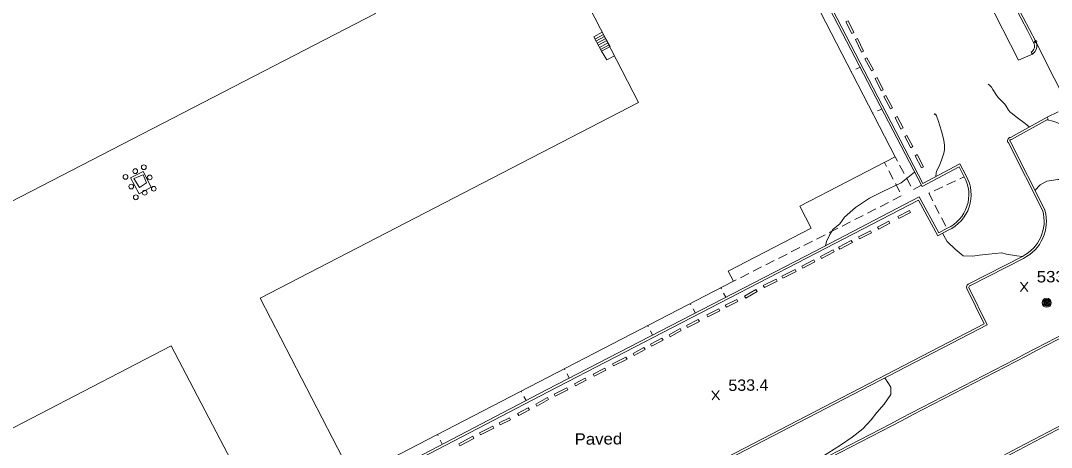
# Model space of a CAD drawing. Extents: x 2361284 to 2366480, y 6976556 to 6985346.
# Drawn here: x 2362953.7 to 2363387.8, y 6978671.2 to 6978850.6 of the extents above; entities that cross this region are included whole.
import ezdxf

# ---------------------------------------------------------------- set-up
doc = ezdxf.new("R2010")
doc.units = 0
doc.header["$LTSCALE"] = 1.9
doc.header["$PDMODE"] = 32
doc.header["$PDSIZE"] = 0.95
for name, color, linetype, lineweight in [('10', 7, 'Continuous', 13), ('12', 7, 'Continuous', 13), ('13', 7, 'Continuous', 13), ('19', 7, 'Continuous', 13), ('26', 7, 'Continuous', 13), ('28', 7, 'Continuous', 13), ('3', 7, 'Continuous', 13), ('31', 7, 'Continuous', 13), ('4', 7, 'Continuous', 13), ('7', 7, 'Continuous', 13)]:
    doc.layers.add(name, color=color, linetype=linetype, lineweight=lineweight)

msp = doc.modelspace()

# ---------------------------------------------------------------- linework, layer by layer
at = {"layer": '10'}
msp.add_lwpolyline([(2363006.791, 6978782.368), (2363005.309, 6978785.755), (2363001.454, 6978784.178), (2363003.739, 6978780.469)], close=True, dxfattribs=at)
at = {"layer": '12'}
for p, q in [((2363377.831, 6978736.766), (2363374.714, 6978740.617)), ((2363374.751, 6978736.737), (2363377.794, 6978740.646)), ((2363247.967, 6978691.149), (2363244.85, 6978695)), ((2363244.887, 6978691.12), (2363247.93, 6978695.029))]:
    msp.add_line(p, q, dxfattribs=at)
at = {"layer": '13'}
for points in [[(2363378.437, 6978805.903), (2363376.724, 6978807.337), (2363373.561, 6978809.727), (2363370.772, 6978811.841), (2363370.404, 6978812.164), (2363369.785, 6978812.922), (2363368.738, 6978814.627), (2363368.156, 6978815.426), (2363365.429, 6978818.32), (2363364.418, 6978819.724), (2363363.185, 6978821.693), (2363362.507, 6978822.642), (2363361.656, 6978823.536), (2363361.135, 6978823.939)], [(2363339.084, 6978785.008), (2363339.274, 6978786.506), (2363339.453, 6978787.242), (2363340.61, 6978789.693), (2363341.655, 6978792.353), (2363342.339, 6978794.397), (2363342.595, 6978795.431), (2363342.744, 6978796.372), (2363342.783, 6978798.281), (2363342.54, 6978800.213), (2363342.258, 6978801.506), (2363341.503, 6978804.081), (2363340.125, 6978808.557), (2363339.376, 6978810.535), (2363338.916, 6978811.276), (2363338.709, 6978811.394), (2363338.435, 6978811.183)], [(2363404.108, 6978795.396), (2363402.878, 6978797.494), (2363401.907, 6978798.87), (2363399.811, 6978801.505), (2363398.173, 6978803.496), (2363397.165, 6978804.25), (2363393.025, 6978806.332), (2363391.326, 6978807.176), (2363389.591, 6978807.909), (2363388.396, 6978808.303), (2363385.949, 6978808.925)], [(2363292.588, 6978755.864), (2363293.021, 6978757.678), (2363294.512, 6978760.692), (2363295.892, 6978762.867), (2363298.67, 6978765.213), (2363300.604, 6978767.901), (2363305.326, 6978772.016), (2363311.129, 6978775.941), (2363316.732, 6978778.815), (2363324.528, 6978782.369), (2363330.166, 6978786.884)], [(2363422.355, 6978734.937), (2363422.362, 6978736.327), (2363422.576, 6978739.069), (2363422.464, 6978741.398), (2363421.917, 6978743.123), (2363421.322, 6978746.817), (2363419.648, 6978750.412), (2363417.403, 6978754.111), (2363414.726, 6978760.005), (2363412.735, 6978765.248), (2363408.669, 6978773.288), (2363406.506, 6978775.698), (2363402.458, 6978779.63), (2363400.805, 6978781.154), (2363397.377, 6978782.981), (2363394.209, 6978783.802), (2363390.438, 6978783.797), (2363385.835, 6978783.082), (2363383.018, 6978781.625), (2363380.851, 6978779.244)], [(2363375.575, 6978751.493), (2363373.223, 6978751.72), (2363368.816, 6978752.409), (2363366.71, 6978752.999), (2363361.425, 6978752.438), (2363357.329, 6978751.949), (2363354.642, 6978751.614), (2363350.621, 6978751.715), (2363347.324, 6978754.504), (2363343.844, 6978757.721), (2363341.931, 6978761.194)], [(2363288.834, 6978664.913), (2363290.436, 6978666.648), (2363293.627, 6978668.739), (2363298.955, 6978672.14), (2363303.845, 6978675.397), (2363308.361, 6978679.01), (2363311.895, 6978682.773), (2363314.316, 6978685.876), (2363317.303, 6978689.315), (2363320.113, 6978693.412), (2363320.204, 6978696.474), (2363317.688, 6978700.34)]]:
    msp.add_lwpolyline(points, dxfattribs=at)
at = {"layer": '19'}
for p, q in [((2363303.601, 6978829.373), (2363303.432, 6978829.291)), ((2363307.225, 6978831.067), (2363305.413, 6978830.22)), ((2363312.718, 6978811.859), (2363312.479, 6978811.757)), ((2363316.403, 6978813.404), (2363314.561, 6978812.626)), ((2363321.993, 6978793.336), (2363322.94, 6978791.575)), ((2363317.475, 6978791.003), (2363318.392, 6978789.232)), ((2363323.887, 6978789.814), (2363325.781, 6978786.292)), ((2363319.309, 6978787.46), (2363321.153, 6978783.908)), ((2363326.728, 6978784.531), (2363328.632, 6978781.008)), ((2363351.065, 6978784.942), (2363349.253, 6978784.095)), ((2363322.07, 6978782.135), (2363323.914, 6978778.583)), ((2363329.705, 6978779.658), (2363333.018, 6978781.389)), ((2363342.005, 6978780.715), (2363338.381, 6978779.03)), ((2363347.44, 6978783.248), (2363343.817, 6978781.562)), ((2363324.55, 6978776.899), (2363320.987, 6978775.085)), ((2363313.862, 6978771.457), (2363310.299, 6978769.643)), ((2363319.205, 6978774.178), (2363315.643, 6978772.364)), ((2363338.728, 6978773.053), (2363340.552, 6978769.491)), ((2363303.172, 6978766.015), (2363299.609, 6978764.202)), ((2363308.518, 6978768.736), (2363304.955, 6978766.922)), ((2363341.469, 6978767.709), (2363343.293, 6978764.147)), ((2363297.828, 6978763.295), (2363294.265, 6978761.491)), ((2363287.14, 6978757.872), (2363283.577, 6978756.068)), ((2363292.483, 6978760.583), (2363288.921, 6978758.779)), ((2363281.795, 6978755.161), (2363278.231, 6978753.357)), ((2363271.105, 6978749.739), (2363267.532, 6978747.935)), ((2363276.45, 6978752.45), (2363272.887, 6978750.646)), ((2363260.408, 6978744.317), (2363256.834, 6978742.513)), ((2363265.751, 6978747.028), (2363262.188, 6978745.224)), ((2363255.052, 6978741.606), (2363253.908, 6978741.025)), ((2363248.798, 6978737.776), (2363248.544, 6978738.243)), ((2363250.702, 6978734.255), (2363249.755, 6978736.016)), ((2363235.94, 6978731.134), (2363235.685, 6978731.592)), ((2363237.904, 6978727.653), (2363236.927, 6978729.394)), ((2363218.008, 6978721.903), (2363217.794, 6978722.341)), ((2363219.802, 6978718.32), (2363218.905, 6978720.112)), ((2363182.947, 6978703.829), (2363182.753, 6978704.207)), ((2363184.771, 6978700.266), (2363183.864, 6978702.048)), ((2363164.696, 6978694.364), (2363164.492, 6978694.753)), ((2363166.58, 6978690.842), (2363165.643, 6978692.603)), ((2363129.509, 6978676.04), (2363129.264, 6978676.537)), ((2363131.263, 6978672.456), (2363130.386, 6978674.248))]:
    msp.add_line(p, q, dxfattribs=at)
msp.add_lwpolyline([(2363336.569, 6978778.193), (2363336.181, 6978778.009), (2363337.811, 6978774.835)], dxfattribs=at)
at = {"layer": '26'}
msp.add_line((2363354.875, 6978871.212), (2363373.87, 6978834.051), dxfattribs=at)
at = {"layer": '28'}
for p, q in [((2363195.058, 6978843.752), (2363198.66, 6978845.726)), ((2363195.537, 6978842.876), (2363199.138, 6978844.85)), ((2363198.66, 6978845.726), (2363201.967, 6978839.677)), ((2363195.058, 6978843.752), (2363198.366, 6978837.703)), ((2363196.015, 6978842.001), (2363199.616, 6978843.975)), ((2363196.503, 6978841.125), (2363200.105, 6978843.1)), ((2363196.982, 6978840.24), (2363200.583, 6978842.214)), ((2363197.46, 6978839.364), (2363201.061, 6978841.339)), ((2363197.938, 6978838.489), (2363201.54, 6978840.463)), ((2363198.366, 6978837.703), (2363201.967, 6978839.677))]:
    msp.add_line(p, q, dxfattribs=at)
at = {"layer": '3'}
for p, q in [((2363301.284, 6978850.087), (2363302.136, 6978850.531)), ((2363301.284, 6978850.087), (2363303.781, 6978845.231)), ((2363302.136, 6978850.531), (2363304.632, 6978845.674)), ((2363303.781, 6978845.231), (2363304.632, 6978845.674)), ((2363305.226, 6978842.684), (2363306.082, 6978843.118)), ((2363305.226, 6978842.684), (2363307.866, 6978837.399)), ((2363306.082, 6978843.118), (2363308.722, 6978837.833)), ((2363380.32, 6978841.339), (2363380.303, 6978841.371)), ((2363381.36, 6978841.393), (2363396.546, 6978811.446)), ((2363307.866, 6978837.399), (2363308.722, 6978837.833)), ((2363373.87, 6978834.051), (2363379.786, 6978836.548)), ((2363379.288, 6978837.363), (2363379.786, 6978836.548)), ((2363309.254, 6978834.582), (2363310.1, 6978835.035)), ((2363309.254, 6978834.582), (2363311.963, 6978829.447)), ((2363310.1, 6978835.035), (2363312.809, 6978829.9)), ((2363311.963, 6978829.447), (2363312.809, 6978829.9)), ((2363313.572, 6978826.282), (2363314.435, 6978826.704)), ((2363313.572, 6978826.282), (2363316.051, 6978821.145)), ((2363314.435, 6978826.704), (2363316.914, 6978821.568)), ((2363316.051, 6978821.145), (2363316.914, 6978821.568)), ((2363317.274, 6978818.727), (2363318.12, 6978819.18)), ((2363317.274, 6978818.727), (2363320.054, 6978813.463)), ((2363318.12, 6978819.18), (2363320.9, 6978813.916)), ((2363320.054, 6978813.463), (2363320.9, 6978813.916)), ((2363321.987, 6978809.912), (2363322.842, 6978810.349)), ((2363321.987, 6978809.912), (2363324.444, 6978805.035)), ((2363322.842, 6978810.349), (2363325.299, 6978805.472)), ((2363390.677, 6978812.33), (2363385.958, 6978810.025)), ((2363386.417, 6978809.179), (2363385.958, 6978810.025)), ((2363324.444, 6978805.035), (2363325.299, 6978805.472)), ((2363326.115, 6978801.91), (2363326.957, 6978802.37)), ((2363326.115, 6978801.91), (2363328.66, 6978797.184)), ((2363326.957, 6978802.37), (2363329.502, 6978797.644)), ((2363328.66, 6978797.184), (2363329.502, 6978797.644)), ((2363330.382, 6978793.811), (2363331.228, 6978794.265)), ((2363330.382, 6978793.811), (2363333.08, 6978788.706)), ((2363331.228, 6978794.265), (2363333.926, 6978789.16)), ((2363333.08, 6978788.706), (2363333.926, 6978789.16)), ((2363327.983, 6978770.759), (2363323.076, 6978768.282)), ((2363327.983, 6978770.759), (2363328.421, 6978769.904)), ((2363319.315, 6978766.237), (2363314.608, 6978763.822)), ((2363319.315, 6978766.237), (2363319.758, 6978765.385)), ((2363323.076, 6978768.282), (2363323.514, 6978767.427)), ((2363328.421, 6978769.904), (2363323.514, 6978767.427)), ((2363311.604, 6978762.224), (2363306.507, 6978759.725)), ((2363311.604, 6978762.224), (2363312.032, 6978761.364)), ((2363314.608, 6978763.822), (2363315.051, 6978762.97)), ((2363319.758, 6978765.385), (2363315.051, 6978762.97)), ((2363303.502, 6978758.195), (2363298.179, 6978755.304)), ((2363303.965, 6978757.354), (2363298.642, 6978754.464)), ((2363303.502, 6978758.195), (2363303.965, 6978757.354)), ((2363306.507, 6978759.725), (2363306.935, 6978758.865)), ((2363312.032, 6978761.364), (2363306.935, 6978758.865)), ((2363295.898, 6978754.192), (2363290.504, 6978751.421)), ((2363296.342, 6978753.341), (2363290.948, 6978750.57)), ((2363295.898, 6978754.192), (2363296.342, 6978753.341)), ((2363298.179, 6978755.304), (2363298.642, 6978754.464)), ((2363287.689, 6978749.994), (2363282.654, 6978747.376)), ((2363288.137, 6978749.145), (2363283.101, 6978746.527)), ((2363287.689, 6978749.994), (2363288.137, 6978749.145)), ((2363290.504, 6978751.421), (2363290.948, 6978750.57)), ((2363279.815, 6978745.969), (2363274.231, 6978743.216)), ((2363280.246, 6978745.111), (2363274.661, 6978742.358)), ((2363279.815, 6978745.969), (2363280.246, 6978745.111)), ((2363282.654, 6978747.376), (2363283.101, 6978746.527)), ((2363271.834, 6978741.933), (2363266.469, 6978739.212)), ((2363272.273, 6978741.08), (2363266.909, 6978738.359)), ((2363271.834, 6978741.933), (2363272.273, 6978741.08)), ((2363274.231, 6978743.216), (2363274.661, 6978742.358)), ((2363263.366, 6978737.482), (2363258.572, 6978734.787)), ((2363263.841, 6978736.648), (2363259.047, 6978733.952)), ((2363263.366, 6978737.482), (2363263.841, 6978736.648)), ((2363266.469, 6978739.212), (2363266.909, 6978738.359)), ((2363255.294, 6978733.396), (2363250.467, 6978730.919)), ((2363255.737, 6978732.544), (2363250.91, 6978730.068)), ((2363255.294, 6978733.396), (2363255.737, 6978732.544)), ((2363258.572, 6978734.787), (2363259.047, 6978733.952)), ((2363247.741, 6978729.453), (2363242.735, 6978726.926)), ((2363248.179, 6978728.599), (2363243.172, 6978726.071)), ((2363247.741, 6978729.453), (2363248.179, 6978728.599)), ((2363250.467, 6978730.919), (2363250.91, 6978730.068)), ((2363239.083, 6978724.981), (2363234.147, 6978722.414)), ((2363239.531, 6978724.132), (2363234.595, 6978721.565)), ((2363239.083, 6978724.981), (2363239.531, 6978724.132)), ((2363242.735, 6978726.926), (2363243.172, 6978726.071)), ((2363231.45, 6978721.118), (2363226.825, 6978718.474)), ((2363226.825, 6978718.474), (2363227.306, 6978717.643)), ((2363231.931, 6978720.288), (2363227.306, 6978717.643)), ((2363231.45, 6978721.118), (2363231.931, 6978720.288)), ((2363234.147, 6978722.414), (2363234.595, 6978721.565)), ((2363223.808, 6978717.026), (2363218.981, 6978714.549)), ((2363218.981, 6978714.549), (2363219.424, 6978713.698)), ((2363224.251, 6978716.174), (2363219.424, 6978713.698)), ((2363223.808, 6978717.026), (2363224.251, 6978716.174)), ((2363216.185, 6978713.132), (2363211.659, 6978710.609)), ((2363211.659, 6978710.609), (2363212.131, 6978709.773)), ((2363216.657, 6978712.296), (2363212.131, 6978709.773)), ((2363216.185, 6978713.132), (2363216.657, 6978712.296)), ((2363208.641, 6978709.08), (2363202.948, 6978706.236)), ((2363202.948, 6978706.236), (2363203.383, 6978705.38)), ((2363209.076, 6978708.224), (2363203.383, 6978705.38)), ((2363208.641, 6978709.08), (2363209.076, 6978708.224)), ((2363199.687, 6978704.455), (2363194.781, 6978701.899)), ((2363194.781, 6978701.899), (2363195.23, 6978701.05)), ((2363200.136, 6978703.607), (2363195.23, 6978701.05)), ((2363199.687, 6978704.455), (2363200.136, 6978703.607)), ((2363191.456, 6978700.208), (2363186.918, 6978697.924)), ((2363186.918, 6978697.924), (2363187.354, 6978697.069)), ((2363191.892, 6978699.352), (2363187.354, 6978697.069)), ((2363191.456, 6978700.208), (2363191.892, 6978699.352)), ((2363183.733, 6978696.213), (2363178.438, 6978693.503)), ((2363178.438, 6978693.503), (2363178.881, 6978692.651)), ((2363184.175, 6978695.361), (2363178.881, 6978692.651)), ((2363183.733, 6978696.213), (2363184.175, 6978695.361)), ((2363175.583, 6978692.125), (2363170.63, 6978689.278)), ((2363170.63, 6978689.278), (2363171.113, 6978688.448)), ((2363176.066, 6978691.296), (2363171.113, 6978688.448)), ((2363175.583, 6978692.125), (2363176.066, 6978691.296)), ((2363159.603, 6978683.643), (2363155.264, 6978681.421)), ((2363159.603, 6978683.643), (2363160.044, 6978682.79)), ((2363167.502, 6978687.838), (2363162.996, 6978685.336)), ((2363162.996, 6978685.336), (2363163.467, 6978684.499)), ((2363167.973, 6978687.002), (2363163.467, 6978684.499)), ((2363167.502, 6978687.838), (2363167.973, 6978687.002)), ((2363152.514, 6978680.076), (2363146.981, 6978677.303)), ((2363152.95, 6978679.221), (2363147.416, 6978676.448)), ((2363152.514, 6978680.076), (2363152.95, 6978679.221)), ((2363155.264, 6978681.421), (2363155.705, 6978680.569)), ((2363160.044, 6978682.79), (2363155.705, 6978680.569)), ((2363144.185, 6978675.806), (2363138.215, 6978672.659)), ((2363144.639, 6978674.96), (2363138.668, 6978671.813)), ((2363144.185, 6978675.806), (2363144.639, 6978674.96)), ((2363146.981, 6978677.303), (2363147.416, 6978676.448)), ((2363138.215, 6978672.659), (2363138.668, 6978671.813))]:
    msp.add_line(p, q, dxfattribs=at)
for points in [[(2363351.062, 6978784.942), (2363351.045, 6978784.962), (2363348.886, 6978789.112), (2363333.293, 6978780.862), (2363289.203, 6978865.778), (2363219.634, 6978999.973), (2363235.096, 6979008.142), (2363235.304, 6979008.225)], [(2363351.901, 6978785.41), (2363351.901, 6978785.41), (2363349.293, 6978790.416), (2363333.701, 6978782.166), (2363290.059, 6978866.216), (2363220.928, 6978999.566), (2363235.544, 6979007.296), (2363235.545, 6979007.295)], [(2363385.958, 6978810.025), (2363370.49, 6978801.537), (2363370.489, 6978801.537)], [(2363386.417, 6978809.179), (2363370.948, 6978800.691), (2363370.651, 6978800.591)], [(2363369.692, 6978799.231), (2363369.69, 6978799.229), (2363384.123, 6978770.625), (2363384.123, 6978770.625)], [(2363370.403, 6978799.875), (2363370.547, 6978799.657), (2363384.979, 6978771.053), (2363385.048, 6978770.884)], [(2363106.232, 6978640.619), (2363106.338, 6978640.307), (2363098.343, 6978655.322), (2363175.407, 6978695.437), (2363288.34, 6978753.653), (2363332.165, 6978776.451), (2363340.338, 6978761.439), (2363343.881, 6978763.293), (2363343.933, 6978763.321)], [(2363107.182, 6978640.755), (2363107.183, 6978640.755), (2363099.647, 6978654.914), (2363175.846, 6978694.581), (2363288.778, 6978752.798), (2363331.777, 6978775.167), (2363339.951, 6978760.154), (2363344.329, 6978762.447), (2363344.329, 6978762.446)], [(2363375.575, 6978751.493), (2363375.575, 6978751.493), (2363353.241, 6978740.14), (2363353.241, 6978740.14)], [(2363375.999, 6978750.632), (2363376.013, 6978750.637), (2363353.68, 6978739.284), (2363353.556, 6978739.233)], [(2363353.066, 6978738.291), (2363353.007, 6978738.457), (2363360.778, 6978722.661), (2363232.792, 6978656.35), (2363126.908, 6978601.42), (2363118.985, 6978616.416), (2363119.095, 6978616.247)], [(2363352.142, 6978738.029), (2363352.141, 6978738.029), (2363359.504, 6978723.079), (2363232.354, 6978657.206), (2363127.316, 6978602.714), (2363119.831, 6978616.864), (2363119.831, 6978616.864)]]:
    msp.add_lwpolyline(points, dxfattribs=at)
msp.add_lwpolyline([(2363008.659, 6978780.515), (2363005.325, 6978787.215), (2363000.031, 6978784.495), (2363003.645, 6978777.788)], close=True, dxfattribs=at)
for centre, radius, start, end in [((2421491.619, 7009084.827), 65468.558, 207.34658, 207.58195), ((2421491.619, 7009084.826), 65467.598, 207.34658, 207.58195), ((2328867.665, 6961054.149), 38826.633, 27.2658, 27.53601), ((2328867.665, 6961054.149), 38827.593, 27.2658, 27.53601), ((2363377.748, 6978839.888), 2.954, 301.39349, 29.42241), ((2363377.748, 6978839.888), 3.914, 301.39349, 29.42241), ((2363370.724, 6978800.165), 1.392, 99.72402, 222.15673), ((2363370.724, 6978800.165), 0.432, 99.724, 222.15671), ((2363337.55, 6978777.412), 15.469, 294.36993, 29.13067), ((2363337.55, 6978777.412), 16.429, 294.36993, 29.13067), ((2363368.322, 6978766.21), 16.407, 296.23647, 15.6125), ((2363368.322, 6978766.21), 17.367, 296.23647, 15.6125), ((2363353.81, 6978738.502), 1.734, 109.13631, 195.82444), ((2363353.81, 6978738.502), 0.773, 109.13629, 195.82442), ((2446851.432, 6817441.355), 181592.243, 117.35268, 117.45168), ((2446851.433, 6817441.355), 181591.283, 117.35268, 117.45168), ((2342834.51, 7017985.293), 44356.191, 297.31294, 297.61226), ((2342834.51, 7017985.293), 44357.151, 297.31294, 297.61226)]:
    msp.add_arc(centre, radius, start, end, dxfattribs=at)
msp.add_point((2363381.156, 6978841.811), dxfattribs=at)
at = {"layer": '31'}
msp.add_lwpolyline([(2363198.366, 6978837.703), (2363200.57, 6978834.144), (2363203.815, 6978835.754)], dxfattribs=at)
at = {"layer": '4'}
for centre, radius in [((2363002.017, 6978787.304), 1), ((2363005.621, 6978788.978), 1), ((2362997.9, 6978784.884), 1), ((2363008.082, 6978784.691), 1), ((2363000.318, 6978780.846), 1), ((2363005.964, 6978778.22), 1), ((2363009.787, 6978779.926), 1), ((2363002.252, 6978776.314), 1), ((2363385.801, 6978731.949), 1.9), ((2363385.801, 6978731.949), 1.442), ((2363385.801, 6978731.949), 0.539), ((2363385.801, 6978731.949), 0.192)]:
    msp.add_circle(centre, radius, dxfattribs=at)
for start, end in [(174.71552, 185.96556), (163.46611, 174.71615), (185.96287, 197.21291), (152.21535, 163.46538), (197.21479, 208.46483), (140.96646, 152.21649), (208.46822, 219.71826), (129.71376, 140.96379), (219.71376, 230.96379), (118.46406, 129.71409), (107.21593, 118.46597), (95.96582, 107.21585), (84.71553, 95.96557), (73.46552, 84.71555), (62.21535, 73.46538), (50.96397, 62.214), (39.71588, 50.96591), (309.71589, 320.96592), (28.46656, 39.7166), (320.96646, 332.21649), (17.21479, 28.46483), (332.21419, 343.46422), (5.96345, 17.21348), (343.46611, 354.71615), (354.71553, 5.96557), (230.96397, 242.214), (242.21812, 253.46815), (253.46258, 264.71261), (264.71553, 275.96557), (275.96582, 287.21585), (287.21593, 298.46597), (298.46406, 309.71409)]:
    msp.add_arc((2363385.801, 6978731.949), 0.973, start, end, dxfattribs=at)
at = {"layer": '7'}
for points in [[(2363054.534, 6978733.96), (2363093.757, 6978658.158), (2363253.908, 6978741.025), (2363251.687, 6978745.325), (2363286.667, 6978763.399), (2363281.899, 6978772.633), (2363321.993, 6978793.336), (2363211.982, 6979006.392), (2363135.971, 6978967.146), (2363213.89, 6978816.239)], [(2363103.109, 6978853.588), (2363068.529, 6978920.703), (2362855.093, 6978810.738), (2362889.673, 6978743.623)]]:
    msp.add_lwpolyline(points, close=True, dxfattribs=at)
msp.add_lwpolyline([(2362927.431, 6978571.542), (2363056.753, 6978638.295), (2363017.084, 6978713.822), (2362888.281, 6978647.134)], dxfattribs=at)

# ---------------------------------------------------------------- texts
at = {"layer": '12'}
for s, width, p in [('533.5', 1.1, (2363381.639, 6978740.49)), ('533.4', 1.05, (2363251.776, 6978694.873))]:
    msp.add_text(s, height=4.799, rotation=0.545, dxfattribs=dict(at, width=width)).set_placement(p)
at = {"layer": '3', "width": 1.1}
msp.add_text('Paved', height=4.799, rotation=0.545, dxfattribs=at).set_placement((2363187.048, 6978672.226))

doc.saveas('drawing.dxf')
